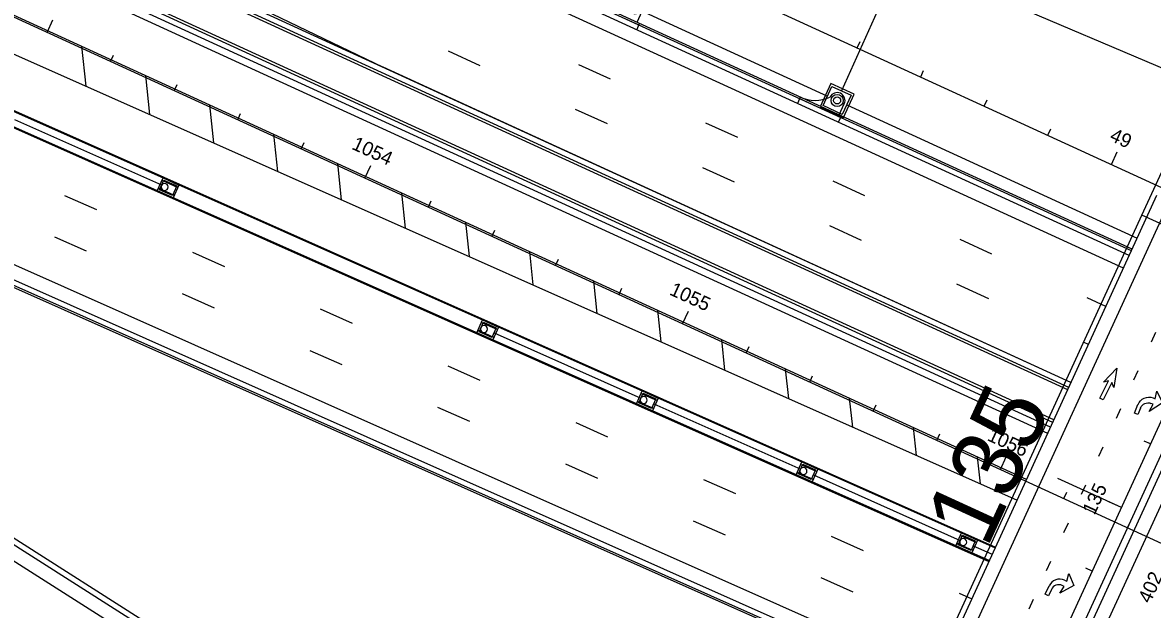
# Model space of a CAD drawing. Extents: x 468143 to 491361, y 1438528 to 1468730.
# Drawn here: x 487597.7 to 487920.8, y 1467031.9 to 1467199.7 of the extents above; entities that cross this region are included whole.
import ezdxf

# ---------------------------------------------------------------- set-up
doc = ezdxf.new("R2010")
doc.units = 0
doc.layers.add('Default', color=7, linetype='Continuous')
doc.layers.add('Xreference_dp', color=7, linetype='Continuous')

# ---------------------------------------------------------------- blocks, each defined once
blk = doc.blocks.new('POINT_DISPLAY')
at = {"layer": 'Default'}
blk.add_line((0, 0), (0, 0), dxfattribs=at)
blk = doc.blocks.new('InltCurb7_40')
at = {"layer": 'Default'}
for p, q in [((2.5, 4), (-2.5, 4)), ((-2.5, 4), (-2.5, 0)), ((2.5, 3.25), (-2.5, 3.25)), ((2.5, 0), (2.5, 4)), ((-2.5, 0.75), (2.5, 0.75)), ((-2.5, 0), (2.5, 0))]:
    blk.add_line(p, q, dxfattribs=at)
blk.add_lwpolyline([(-2, 0.5), (2, 0.5), (2, 3.5), (-2, 3.5)], close=True, dxfattribs=at)
blk.add_circle((-1.04, 2.19), 1, dxfattribs=at)
for p in [(-2, 3.5), (0, 4), (0, 3.5), (0, 3.5), (2, 3.5), (-2, 2), (-2, 2), (-2, 0.5), (0, 2), (0, 2), (0, 0.5), (0, 0.5), (0, 0), (0, 0), (2, 2), (2, 2), (2, 0.5)]:
    blk.add_blockref('POINT_DISPLAY', p, dxfattribs=at)
blk = doc.blocks.new('InltCurb1_35')
at = {"layer": 'Default'}
for p, q in [((2.25, 2), (2.25, 5.5)), ((-10, 2), (-10, 0)), ((-10, 1.5), (3, 1.5)), ((3, 2), (2.25, 2)), ((3, 0), (3, 2))]:
    blk.add_line(p, q, dxfattribs=at)
for radius in [1.75, 1]:
    blk.add_circle((0, 5.5), radius, dxfattribs=at)
for centre, radius, start, end in [((0, 5.5), 2.25, 0, 180), ((-9.85, 12), 10, 269.1432, 319.4677)]:
    blk.add_arc(centre, radius, start, end, dxfattribs=at)
for p in [(-1.22, 6.76), (-0.66, 7.12), (0, 7.75), (0, 7.25), (0, 7.25), (0.7, 7.1), (1.26, 6.72), (-1.75, 5.5), (-1.75, 5.5), (-1.62, 4.84), (-1.6, 6.2), (-1.26, 4.28), (-0.7, 3.9), (0, 5.5), (0, 5.5), (0, 3.75), (0, 3.75), (0.66, 3.88), (1.22, 4.24), (1.6, 4.8), (1.62, 6.16), (1.75, 5.5), (1.75, 5.5), (0, 0), (0, 0)]:
    blk.add_blockref('POINT_DISPLAY', p, dxfattribs=at)
blk = doc.blocks.new('JBottom60x60')
at = {"layer": 'Default'}
for p, q in [((3.67, 3.67), (-3.67, 3.67)), ((-3.67, 3.67), (-3.67, -3.67)), ((3.67, -3.67), (3.67, 3.67)), ((-3, -3), (-3, 3)), ((-3, 3), (3, 3)), ((3, 3), (3, -3)), ((3, -3), (-3, -3)), ((-3.67, -3.67), (3.67, -3.67))]:
    blk.add_line(p, q, dxfattribs=at)
for p in [(-3, 3), (-3, 0), (-3, 0), (0, 3), (0, 3), (0, 3), (0, 0), (0, 0), (0, 0), (3, 3), (3, 0), (3, 0), (-3, -3), (0, -3), (0, -3), (0, -3), (3, -3)]:
    blk.add_blockref('POINT_DISPLAY', p, dxfattribs=at)
blk = doc.blocks.new('DAMerge_2')
at = {"layer": 'Default'}
blk.add_lwpolyline([(0.71, -4.09), (0, -3.39), (3.95, 0.56), (2.42, 0.68), (7.31, 3.21), (4.77, -1.68), (4.66, -0.15), (0.71, -4.09)], dxfattribs=at)
blk = doc.blocks.new('DALeftTurn_4_1')
at = {"layer": 'Default'}
for points in [[(5.67, 3.17), (2, 0.5), (4.33, 0.83), (4.33, 0.17)], [(6, 0.17), (6, 0.83), (8.25, 0.5), (5.67, 3.17)], [(2, -2.17), (0, -2.17), (0, -3.17), (2.67, -3.17)]]:
    blk.add_lwpolyline(points, dxfattribs=at)
for centre, radius in [((2, 0.17), 2.33), ((2.67, 0.17), 3.33)]:
    blk.add_arc(centre, radius, 270, 0, dxfattribs=at)
blk = doc.blocks.new('DARightTurn_4')
at = {"layer": 'Default'}
for points in [[(2, 2.17), (0, 2.17), (0, 3.17), (2.67, 3.17)], [(5.67, -3.17), (2, -0.5), (4.33, -0.83), (4.33, -0.17)], [(6, -0.17), (6, -0.83), (8.25, -0.5), (5.67, -3.17)]]:
    blk.add_lwpolyline(points, dxfattribs=at)
for centre, radius in [((2, -0.17), 2.33), ((2.67, -0.17), 3.33)]:
    blk.add_arc(centre, radius, 360, 90, dxfattribs=at)
blk = doc.blocks.new('DAMerge_6')
at = {"layer": 'Default'}
blk.add_lwpolyline([(0.71, -4.09), (0, -3.39), (3.95, 0.56), (2.42, 0.68), (7.31, 3.21), (4.77, -1.68), (4.66, -0.15), (0.71, -4.09)], dxfattribs=at)
blk = doc.blocks.new('DALeftTurn_5')
at = {"layer": 'Default'}
for points in [[(5.67, 3.17), (2, 0.5), (4.33, 0.83), (4.33, 0.17)], [(6, 0.17), (6, 0.83), (8.25, 0.5), (5.67, 3.17)], [(2, -2.17), (0, -2.17), (0, -3.17), (2.67, -3.17)]]:
    blk.add_lwpolyline(points, dxfattribs=at)
for centre, radius in [((2, 0.17), 2.33), ((2.67, 0.17), 3.33)]:
    blk.add_arc(centre, radius, 270, 0, dxfattribs=at)

msp = doc.modelspace()

# ---------------------------------------------------------------- linework, layer by layer
at = {"layer": 'Xreference_dp'}
for p, q in [((487372.29, 1467405.61), (488386.67, 1466939.92)), ((487896.62, 1467094.69), (487480.46, 1467285.51)), ((487896.93, 1467095.38), (487480.75, 1467286.21)), ((487897.55, 1467096.74), (487481.23, 1467287.63)), ((487416.58, 1467283.18), (488348.99, 1466855.64)), ((487891.72, 1467084.01), (487460.98, 1467281.52)), ((487892.34, 1467085.38), (487461.6, 1467282.88)), ((487892.66, 1467086.06), (487461.92, 1467283.57)), ((487890.89, 1467082.19), (487460.14, 1467279.7)), ((487914.85, 1467134.46), (487608.65, 1467274.87)), ((487915.06, 1467134.92), (487608.86, 1467275.32)), ((487884.84, 1467069.01), (487440.18, 1467272.9)), ((487520.69, 1467273.94), (487700.82, 1467186.95)), ((487914.23, 1467133.1), (487608.02, 1467273.5)), ((487435.5, 1467261.72), (487882.12, 1467063.09)), ((487859.77, 1466947.15), (487993.45, 1467238.69)), ((487859.77, 1466947.15), (487993.45, 1467238.69)), ((487307.99, 1467233.04), (487708.93, 1466978.07)), ((487305.02, 1467230.19), (487766.73, 1466936.58)), ((487471.86, 1467229.11), (487875.87, 1467049.46)), ((487471.96, 1467229.34), (487875.98, 1467049.69)), ((487856.07, 1466996.67), (487960.96, 1467225.43)), ((487802.71, 1467179.83), (487715.83, 1467219.67)), ((487847.86, 1467215.79), (487831.91, 1467180.19)), ((487936.77, 1467181.05), (487859.2, 1467214.13)), ((487604.66, 1467196.93), (487606.33, 1467200.57)), ((487774.49, 1467203.22), (487827.93, 1467178.72)), ((487527.87, 1467199.55), (487874.1, 1467045.59)), ((487528.34, 1467199.61), (487874.21, 1467045.82)), ((487917.83, 1467144.65), (487942.3, 1467198.03)), ((487836.39, 1467192.54), (487837.23, 1467194.36)), ((487614.51, 1467192.97), (487615.72, 1467181.57)), ((487728.59, 1467187.42), (487719.5, 1467191.58)), ((487622.84, 1467188.6), (487623.68, 1467190.42)), ((487765.87, 1467183.52), (487756.78, 1467187.69)), ((487632.81, 1467184.58), (487633.99, 1467173.44)), ((487897.55, 1467096.74), (487700.82, 1467186.95)), ((487854.57, 1467184.2), (487855.4, 1467186.02)), ((487641.02, 1467180.26), (487641.86, 1467182.08)), ((487912.56, 1467129.46), (487802.71, 1467179.83)), ((487651.12, 1467176.18), (487652.26, 1467165.31)), ((487764.95, 1467170.74), (487755.86, 1467174.91)), ((487833.39, 1467176.22), (487916.52, 1467138.1)), ((487872.75, 1467175.86), (487873.58, 1467177.67)), ((487637.47, 1467153.28), (487595.44, 1467171.97)), ((487659.2, 1467171.93), (487660.04, 1467173.74)), ((487802.23, 1467166.85), (487793.14, 1467171.02)), ((487890.92, 1467167.51), (487891.76, 1467169.33)), ((487669.42, 1467167.79), (487670.54, 1467157.19)), ((487677.38, 1467163.59), (487678.22, 1467165.41)), ((487909.1, 1467159.17), (487910.77, 1467162.8)), ((487687.72, 1467159.4), (487688.81, 1467149.06)), ((487695.56, 1467155.25), (487697.23, 1467158.89)), ((487801.31, 1467154.07), (487792.22, 1467158.24)), ((487838.59, 1467150.18), (487829.5, 1467154.35)), ((487553.17, 1467149.17), (487859.2, 1467013.1)), ((487609.68, 1467150.31), (487618.82, 1467146.25)), ((487706.03, 1467151.01), (487707.09, 1467140.93)), ((487849.18, 1466991.24), (487922.15, 1467150.37)), ((487713.74, 1467146.92), (487714.58, 1467148.74)), ((487550.74, 1467143.69), (487856.7, 1467007.64)), ((487550.94, 1467144.15), (487856.91, 1467008.1)), ((487551.55, 1467145.52), (487857.53, 1467009.46)), ((487724.33, 1467142.61), (487725.36, 1467132.8)), ((487850.72, 1466998.3), (487917.83, 1467144.65)), ((487972.84, 1467119.42), (487917.83, 1467144.65)), ((487731.92, 1467138.58), (487732.76, 1467140.4)), ((487837.67, 1467137.4), (487828.58, 1467141.57)), ((487606.74, 1467138.49), (487615.88, 1467134.42)), ((487859.77, 1466947.15), (487947.63, 1467138.77)), ((487874.95, 1467133.51), (487865.86, 1467137.67)), ((487646.23, 1467134.06), (487655.37, 1467130)), ((487742.63, 1467134.22), (487743.64, 1467124.68)), ((487878.29, 1466977.96), (487949.29, 1467132.79)), ((487750.1, 1467130.25), (487750.94, 1467132.06)), ((487880.11, 1466977.12), (487949.02, 1467127.41)), ((487760.93, 1467125.83), (487761.91, 1467116.55)), ((487768.28, 1467121.91), (487769.12, 1467123.73)), ((487874.03, 1467120.73), (487864.94, 1467124.9)), ((487883.23, 1466974.33), (487952.66, 1467125.74)), ((487643.29, 1467122.23), (487652.43, 1467118.17)), ((487907.56, 1467118.55), (487902.22, 1467121)), ((487682.78, 1467117.81), (487691.92, 1467113.75)), ((487779.24, 1467117.44), (487780.19, 1467108.42)), ((487786.46, 1467113.57), (487788.13, 1467117.21)), ((487732.51, 1467111.02), (487774.54, 1467092.33)), ((487921.72, 1467111.05), (487920.47, 1467108.32)), ((487797.54, 1467109.04), (487798.46, 1467100.29)), ((487804.64, 1467105.24), (487805.48, 1467107.06)), ((487902.56, 1467107.65), (487901.3, 1467108.22)), ((487679.84, 1467105.98), (487688.98, 1467101.92)), ((487719.33, 1467101.56), (487728.47, 1467097.49)), ((487815.84, 1467100.65), (487816.74, 1467092.16)), ((487822.82, 1467096.9), (487823.66, 1467098.72)), ((487916.72, 1467100.14), (487915.47, 1467097.41)), ((487778.2, 1467090.7), (487820.23, 1467072.01)), ((487834.15, 1467092.26), (487835.01, 1467084.04)), ((487716.39, 1467089.73), (487725.53, 1467085.67)), ((487841, 1467088.57), (487841.84, 1467090.38)), ((487911.71, 1467089.23), (487910.46, 1467086.5)), ((487755.88, 1467085.3), (487765.02, 1467081.24)), ((487852.45, 1467083.87), (487853.29, 1467075.91)), ((487859.18, 1467080.23), (487860.02, 1467082.05)), ((487906.71, 1467078.32), (487905.46, 1467075.6)), ((487920.31, 1467079.19), (487918.49, 1467080.03)), ((487870.75, 1467075.47), (487871.56, 1467067.78)), ((487877.36, 1467071.89), (487879.03, 1467075.53)), ((487752.94, 1467073.48), (487762.08, 1467069.42)), ((487792.43, 1467069.05), (487801.57, 1467064.99)), ((487823.89, 1467070.38), (487865.81, 1467051.54)), ((487911.98, 1467061.01), (487893.8, 1467069.35)), ((487574.75, 1467065.23), (487709.71, 1466979.4)), ((487895.54, 1467063.56), (487896.38, 1467065.38)), ((487901.71, 1467067.42), (487900.46, 1467064.69)), ((487911.98, 1467061.01), (487908.34, 1467062.68)), ((487789.49, 1467057.23), (487798.63, 1467053.16)), ((487896.71, 1467056.51), (487895.46, 1467053.78)), ((487913.72, 1467055.22), (487914.55, 1467057.04)), ((487828.98, 1467052.8), (487838.12, 1467048.74)), ((487869.58, 1467050.07), (487875.04, 1467047.64)), ((487891.71, 1467045.6), (487890.46, 1467042.87)), ((487903.64, 1467042.83), (487901.82, 1467043.67)), ((487826.04, 1467040.97), (487835.18, 1467036.91)), ((487865.53, 1467036.55), (487869.21, 1467034.91)), ((487886.71, 1467034.69), (487885.46, 1467031.97))]:
    msp.add_line(p, q, dxfattribs=at)

# ---------------------------------------------------------------- block references
for name, p, rotation in [('InltCurb1_35', (487770.6, 1467198.95), -24.632880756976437), ('InltCurb1_35', (487828.37, 1467172.47), -24.632880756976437), ('JBottom60x60', (487830.66, 1467177.47), 65.36711924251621), ('DAMerge_2', (487904.75, 1467095.46), 18.64298397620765), ('DAMerge_6', (487904.75, 1467095.46), 18.64298397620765), ('DARightTurn_4', (487893.08, 1467034.86), 65.36711924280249)]:
    msp.add_blockref(name, p, dxfattribs=dict(at, rotation=rotation))
for name, p, yscale, rotation in [('InltCurb7_40', (487640.11, 1467154.29), -0.9999999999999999, -23.972703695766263), ('InltCurb7_40', (487731.49, 1467113.66), -0.9999999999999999, -23.972703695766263), ('InltCurb7_40', (487777.18, 1467093.34), -0.9999999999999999, -23.972703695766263), ('DALeftTurn_4_1', (487918.71, 1467086.83), -1, 68.82662784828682), ('DALeftTurn_5', (487918.71, 1467086.83), -1, 68.82662784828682), ('InltCurb7_40', (487822.87, 1467073.02), -0.9999999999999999, -23.972703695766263), ('InltCurb7_40', (487868.56, 1467052.71), -0.9999999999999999, -23.972703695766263)]:
    msp.add_blockref(name, p, dxfattribs=dict(at, yscale=yscale, rotation=rotation))

# ---------------------------------------------------------------- texts
for s, height, rotation, p in [('49', 4, 335.3408, (487908.34, 1467166.12)), ('1054', 4, 335.3671, (487691.53, 1467163.7)), ('1055', 4, 335.3671, (487782.43, 1467122.02)), ('135', 20, 65.3671, (487873.48, 1467049.03)), ('1056', 4, 335.3671, (487873.33, 1467080.34)), ('135', 4, 65.3671, (487904.28, 1467058.62)), ('402', 4, 65.3671, (487920.19, 1467033.35))]:
    msp.add_text(s, height=height, rotation=rotation, dxfattribs=at).set_placement(p)

doc.saveas('drawing.dxf')
